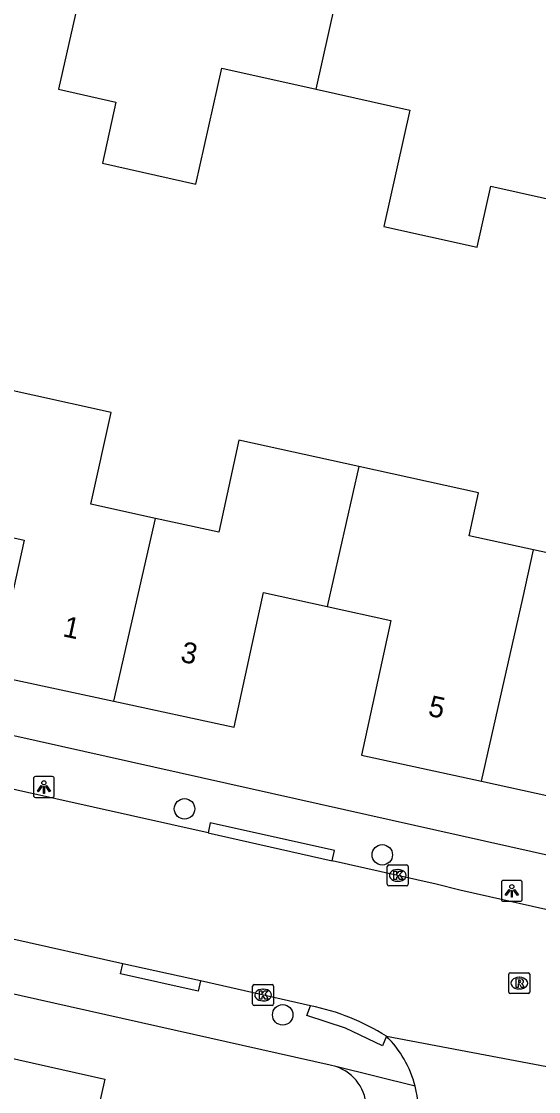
# Model space of a CAD drawing. Extents: x 161771 to 163125, y 382479 to 383177.
# Drawn here: x 162626.6 to 162651.4, y 382690.8 to 382742 of the extents above; entities that cross this region are included whole.
import ezdxf

# ---------------------------------------------------------------- set-up
doc = ezdxf.new("R2010")
doc.units = 0
for name, color, linetype in [('IMGEO_Boom', 7, 'Continuous'), ('IMGEO_Kolk', 7, 'Continuous'), ('IMGEO_Lichtpunt', 7, 'Continuous'), ('IMGEO_Pand', 7, 'Continuous'), ('IMGEO_Pand_nummerreeks', 7, 'Continuous'), ('IMGEO_Rijbaan_lokaal_open', 7, 'Continuous'), ('IMGEO_Rioolput', 7, 'Continuous'), ('IMGEO_Voetpad_open', 7, 'Continuous')]:
    doc.layers.add(name, color=color, linetype=linetype)

msp = doc.modelspace()

# ---------------------------------------------------------------- linework, layer by layer
at = {"layer": 'IMGEO_Boom'}
for centre in [(162634.413, 382704.345), (162643.876, 382702.147), (162639.111, 382694.492)]:
    msp.add_circle(centre, 0.489, dxfattribs=at)
at = {"layer": 'IMGEO_Kolk'}
for p, q in [((162644.115, 382700.737), (162644.115, 382701.589)), ((162644.19, 382701.663), (162645.042, 382701.663)), ((162644.603, 382701.443), (162644.628, 382701.443)), ((162645.116, 382701.589), (162645.116, 382700.737)), ((162645.042, 382700.663), (162644.19, 382700.663)), ((162644.626, 382700.883), (162644.601, 382700.883)), ((162637.672, 382695.016), (162637.672, 382695.868)), ((162637.747, 382695.942), (162638.599, 382695.942)), ((162638.673, 382695.868), (162638.673, 382695.016)), ((162638.16, 382695.722), (162638.185, 382695.722)), ((162638.599, 382694.942), (162637.747, 382694.942)), ((162638.183, 382695.162), (162638.158, 382695.162))]:
    msp.add_line(p, q, dxfattribs=at)
for points in [[(162644.115, 382700.737), (162644.115, 382701.589)], [(162644.19, 382701.663), (162645.042, 382701.663)], [(162645.116, 382701.589), (162645.116, 382700.737)], [(162644.436, 382701.363), (162644.559, 382701.363), (162644.559, 382701.212), (162644.689, 382701.363), (162644.853, 382701.363), (162644.707, 382701.212), (162644.86, 382700.963), (162644.708, 382700.963), (162644.623, 382701.127), (162644.559, 382701.06), (162644.559, 382700.963), (162644.436, 382700.963), (162644.436, 382701.363)], [(162645.042, 382700.663), (162644.19, 382700.663)], [(162637.672, 382695.016), (162637.672, 382695.868)], [(162637.747, 382695.942), (162638.599, 382695.942)], [(162638.673, 382695.868), (162638.673, 382695.016)], [(162637.993, 382695.642), (162638.116, 382695.642), (162638.116, 382695.491), (162638.246, 382695.642), (162638.41, 382695.642), (162638.264, 382695.491), (162638.417, 382695.242), (162638.265, 382695.242), (162638.18, 382695.406), (162638.116, 382695.339), (162638.116, 382695.242), (162637.993, 382695.242), (162637.993, 382695.642)], [(162638.599, 382694.942), (162637.747, 382694.942)]]:
    msp.add_lwpolyline(points, dxfattribs=at)
for centre, start, end in [((162644.192, 382701.587), 91.552, 178.448), ((162644.192, 382701.587), 91.552, 178.448), ((162645.04, 382701.587), 1.552, 88.448), ((162645.04, 382701.587), 1.552, 88.448), ((162644.192, 382700.739), 181.552, 268.448), ((162644.192, 382700.739), 181.552, 268.448), ((162645.04, 382700.739), 271.552, 358.448), ((162645.04, 382700.739), 271.552, 358.448), ((162637.749, 382695.866), 91.552, 178.448), ((162637.749, 382695.866), 91.552, 178.448), ((162638.597, 382695.866), 1.552, 88.448), ((162638.597, 382695.866), 1.552, 88.448), ((162637.749, 382695.018), 181.552, 268.448), ((162637.749, 382695.018), 181.552, 268.448), ((162638.597, 382695.018), 271.552, 358.448), ((162638.597, 382695.018), 271.552, 358.448)]:
    msp.add_arc(centre, 0.0765, start, end, dxfattribs=at)
for centre, major_axis, ratio, start_param, end_param in [((162644.602, 382701.163), (-0.387, 0.002), 0.722429, 4.712389, 7.853982), ((162644.627, 382701.163), (-0.39, 0.002), 0.717154, 1.570796, 4.712389), ((162638.159, 382695.442), (-0.387, 0.002), 0.722429, 4.712389, 7.853982), ((162638.184, 382695.442), (-0.39, 0.002), 0.717154, 1.570796, 4.712389)]:
    msp.add_ellipse(centre, major_axis=major_axis, ratio=ratio, start_param=start_param, end_param=end_param, dxfattribs=at)
at = {"layer": 'IMGEO_Lichtpunt'}
for p, q in [((162627.183, 382705.792), (162627.183, 382704.985)), ((162627.183, 382705.792), (162627.183, 382704.985)), ((162628.085, 382705.887), (162627.277, 382705.887)), ((162628.085, 382705.887), (162627.277, 382705.887)), ((162628.179, 382704.985), (162628.179, 382705.792)), ((162628.179, 382704.985), (162628.179, 382705.792)), ((162627.277, 382704.891), (162628.085, 382704.891)), ((162627.277, 382704.891), (162628.085, 382704.891)), ((162650.478, 382700.922), (162649.67, 382700.922)), ((162650.478, 382700.922), (162649.67, 382700.922)), ((162649.576, 382700.827), (162649.576, 382700.02)), ((162649.576, 382700.827), (162649.576, 382700.02)), ((162650.572, 382700.02), (162650.572, 382700.827)), ((162650.572, 382700.02), (162650.572, 382700.827)), ((162649.67, 382699.926), (162650.478, 382699.926)), ((162649.67, 382699.926), (162650.478, 382699.926))]:
    msp.add_line(p, q, dxfattribs=at)
for points in [[(162627.557, 382705.456), (162627.596, 382705.428), (162627.408, 382705.166), (162627.37, 382705.193), (162627.557, 382705.456)], [(162627.659, 382705.408), (162627.706, 382705.408), (162627.706, 382705.086), (162627.659, 382705.086), (162627.659, 382705.408)], [(162627.769, 382705.428), (162627.807, 382705.455), (162627.994, 382705.193), (162627.955, 382705.165), (162627.769, 382705.428)], [(162649.95, 382700.491), (162649.989, 382700.463), (162649.801, 382700.201), (162649.763, 382700.228), (162649.95, 382700.491)], [(162650.052, 382700.443), (162650.099, 382700.443), (162650.099, 382700.121), (162650.052, 382700.121), (162650.052, 382700.443)], [(162650.162, 382700.463), (162650.2, 382700.49), (162650.387, 382700.228), (162650.348, 382700.2), (162650.162, 382700.463)]]:
    msp.add_lwpolyline(points, dxfattribs=at)
for centre in [(162627.682, 382705.59), (162650.075, 382700.625)]:
    msp.add_circle(centre, 0.0994, dxfattribs=at)
for centre, start, end in [((162627.277, 382705.792), 90, 180), ((162627.277, 382705.792), 90, 180), ((162628.085, 382705.792), 0, 90), ((162628.085, 382705.792), 0, 90), ((162627.277, 382704.985), 180, 270), ((162627.277, 382704.985), 180, 270), ((162628.085, 382704.985), 270, 0), ((162628.085, 382704.985), 270, 360), ((162649.67, 382700.827), 90, 180), ((162649.67, 382700.827), 90, 180), ((162650.478, 382700.827), 0, 90), ((162650.478, 382700.827), 0, 90), ((162649.67, 382700.02), 180, 270), ((162649.67, 382700.02), 180, 270), ((162650.478, 382700.02), 270, 0), ((162650.478, 382700.02), 270, 360)]:
    msp.add_arc(centre, 0.0946, start, end, dxfattribs=at)
at = {"layer": 'IMGEO_Pand'}
for points in [[(162642.534, 382746.916), (162640.042, 382747.473), (162640.606, 382750), (162640.761, 382750.693), (162634.261, 382752.144), (162633.782, 382750), (162633.091, 382746.904), (162630.35, 382747.518), (162629.254, 382742.64), (162628.382, 382738.757), (162631.128, 382738.141), (162630.486, 382735.218), (162634.953, 382734.217), (162636.199, 382739.776), (162640.71, 382738.765)], [(162640.71, 382738.765), (162642.534, 382746.916)], [(162640.71, 382738.765), (162645.2, 382737.759), (162643.954, 382732.2), (162648.411, 382731.201), (162649.067, 382734.127), (162651.787, 382733.517)], [(162633.027, 382718.235), (162629.934, 382718.911), (162630.895, 382723.307), (162625.191, 382724.554), (162624.789, 382722.764), (162623.693, 382717.885), (162626.74, 382717.201), (162625.297, 382710.728), (162631.034, 382709.491)], [(162642.756, 382720.713), (162637.011, 382721.97), (162636.05, 382717.574), (162633.027, 382718.235)], [(162642.756, 382720.713), (162641.246, 382714.025)], [(162651.12, 382716.735), (162648.032, 382717.41), (162648.48, 382719.461), (162642.756, 382720.713)], [(162631.034, 382709.491), (162633.027, 382718.235)], [(162660.347, 382716.866), (162654.576, 382718.128), (162654.128, 382716.077), (162651.12, 382716.735)], [(162648.625, 382705.662), (162650.6, 382714.4), (162651.12, 382716.735)], [(162631.034, 382709.491), (162636.784, 382708.252), (162638.193, 382714.693), (162641.246, 382714.025)], [(162641.246, 382714.025), (162644.291, 382713.359), (162642.882, 382706.918), (162648.625, 382705.662)], [(162648.625, 382705.662), (162654.367, 382704.406), (162655.776, 382710.847), (162658.837, 382710.177)], [(162623.107, 382687.052), (162624.403, 382692.807), (162630.598, 382691.412), (162629.302, 382685.657), (162632.278, 382684.987)]]:
    msp.add_lwpolyline(points, dxfattribs=at)
at = {"layer": 'IMGEO_Rijbaan_lokaal_open'}
for points in [[(162635.538, 382703.194), (162624.526, 382705.646), (162624.317, 382705.698)], [(162635.538, 382703.194), (162641.482, 382701.86)], [(162653.124, 382699.219), (162647.581, 382700.462), (162646.46, 382700.739), (162644.611, 382701.162), (162641.482, 382701.86)], [(162631.452, 382696.941), (162626.058, 382698.138)], [(162635.178, 382696.118), (162631.452, 382696.941)], [(162640.448, 382694.931), (162635.178, 382696.118)], [(162644.071, 382693.474), (162653.521, 382691.693)]]:
    msp.add_lwpolyline(points, dxfattribs=at)
for centre, radius, start, end in [((162638.211, 382684.136), 11.024, 57.8911, 78.2935), ((162640.498, 382689.831), 5.103, 14.1607, 45.5607), ((162640.514, 382689.833), 5.086, 352.9973, 14.1783)]:
    msp.add_arc(centre, radius, start, end, dxfattribs=at)
at = {"layer": 'IMGEO_Rioolput'}
for p, q in [((162649.933, 382695.584), (162649.933, 382696.436)), ((162650.008, 382696.51), (162650.86, 382696.51)), ((162650.421, 382696.29), (162650.446, 382696.29)), ((162650.934, 382696.436), (162650.934, 382695.584)), ((162650.86, 382695.51), (162650.008, 382695.51)), ((162650.444, 382695.73), (162650.419, 382695.73))]:
    msp.add_line(p, q, dxfattribs=at)
for points in [[(162649.933, 382695.584), (162649.933, 382696.436)], [(162650.008, 382696.51), (162650.86, 382696.51)], [(162650.934, 382696.436), (162650.934, 382695.584)], [(162650.522, 382696.208), (162650.27, 382696.21), (162650.27, 382695.81)], [(162650.27, 382695.81), (162650.394, 382695.81), (162650.394, 382695.972), (162650.405, 382695.972)], [(162650.448, 382696.129), (162650.394, 382696.129), (162650.394, 382696.048)], [(162650.394, 382696.048), (162650.446, 382696.048)], [(162650.452, 382695.943), (162650.523, 382695.81), (162650.663, 382695.81), (162650.598, 382695.936)], [(162650.86, 382695.51), (162650.008, 382695.51)]]:
    msp.add_lwpolyline(points, dxfattribs=at)
for centre, radius, start, end in [((162650.01, 382696.434), 0.0765, 91.552, 178.448), ((162650.01, 382696.434), 0.0765, 91.552, 178.448), ((162650.858, 382696.434), 0.0765, 1.552, 88.448), ((162650.858, 382696.434), 0.0765, 1.552, 88.448), ((162650.404, 382695.919), 0.0533, 26.0293, 88.6989), ((162650.43, 382696.237), 0.19, 274.7715, 282.9687), ((162650.454, 382696.033), 0.0964, 77.0061, 93.1865), ((162650.468, 382696.09), 0.0378, 276.6634, 79.6772), ((162650.521, 382696.098), 0.109, 350.3612, 89.416), ((162650.519, 382696.098), 0.112, 277.5842, 350.9817), ((162650.503, 382695.883), 0.108, 29.5134, 73.7905), ((162650.01, 382695.586), 0.0765, 181.552, 268.448), ((162650.01, 382695.586), 0.0765, 181.552, 268.448), ((162650.858, 382695.586), 0.0765, 271.552, 358.448), ((162650.858, 382695.586), 0.0765, 271.552, 358.448)]:
    msp.add_arc(centre, radius, start, end, dxfattribs=at)
for centre, major_axis, ratio, start_param, end_param in [((162650.42, 382696.01), (-0.387, 0.002), 0.722429, 4.712389, 7.853982), ((162650.445, 382696.01), (-0.39, 0.002), 0.717154, 1.570796, 4.712389)]:
    msp.add_ellipse(centre, major_axis=major_axis, ratio=ratio, start_param=start_param, end_param=end_param, dxfattribs=at)
at = {"layer": 'IMGEO_Voetpad_open'}
for points in [[(162611.862, 382711.117), (162621.667, 382708.866), (162687.264, 382694.2), (162689.87, 382693.601)], [(162641.482, 382701.86), (162641.591, 382702.347), (162635.647, 382703.681), (162635.538, 382703.194)], [(162641.661, 382692.016), (162641.382, 382692.085), (162597.639, 382701.888), (162596.769, 382702.121)], [(162635.178, 382696.118), (162635.071, 382695.63), (162631.345, 382696.453), (162631.452, 382696.941)], [(162644.071, 382693.474), (162643.885, 382693.011), (162642.122, 382693.859), (162640.262, 382694.468), (162640.448, 382694.931)], [(162645.446, 382691.079), (162641.661, 382692.016)]]:
    msp.add_lwpolyline(points, dxfattribs=at)
msp.add_arc((162641.019, 382690.023), 2.094, 358.3536, 72.1495, dxfattribs=at)

# ---------------------------------------------------------------- texts
at = {"layer": 'IMGEO_Pand_nummerreeks'}
for s, rotation, p in [('1', 347.8361, (162628.543, 382712.607)), ('3', 347.8361, (162634.174, 382711.393)), ('5', 347.6625, (162646.023, 382708.81))]:
    msp.add_text(s, height=1, rotation=rotation, dxfattribs=at).set_placement(p)

doc.saveas('drawing.dxf')
